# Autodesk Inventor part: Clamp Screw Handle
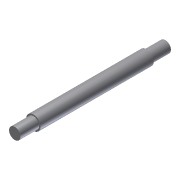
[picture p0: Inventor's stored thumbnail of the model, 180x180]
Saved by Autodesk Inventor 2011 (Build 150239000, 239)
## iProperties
Shininess: 77.0
Length Units: 11269
Angle Units: 11279
Time Units: 11290
Mass Units: 11283
Length Display Precision: 3
Angle Display Precision: 2
Compacted: True
Created: 2002-02
Part Number: Clamp Screw Handle
Document SubType Name: Modeling
Designer: ***
Density: 1 g/cm^3
Density: 0.0
Volumn: 0.0
Area: 0.0
PropertySet Name: Model Information
Control State: 0
Master: False
Checked Out: False
Author: ***
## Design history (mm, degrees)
sketch "Sketch1"
  geometry: L1 (0, 105)-(4, 105); L2 (4, 105)-(4, 92); L3 (4, 92)-(5, 92); L4 (5, 92)-(5, 13); L5 (5, 13)-(4, 13); L6 (4, 13)-(4, 0); L7 (4, 0)-(0, 0); L8 (0, 0)-(0, 105)
  constraints: 16 end point, 5 parallel, 2 equal length, 1 collinear, 1 horizontal, 1 perpendicular
  dimensions: "d0" = 10 diameter of L4 L8; "d1" = 8 diameter of L2 L8; "d2" = 13 distance of L1.end L2.end; "d3" = 79 distance of L3.end L4.end
revolve "Revolution1" sketch "Sketch1" stored, may be unused: angle "d4" = 90 deg
body "Solid1"
